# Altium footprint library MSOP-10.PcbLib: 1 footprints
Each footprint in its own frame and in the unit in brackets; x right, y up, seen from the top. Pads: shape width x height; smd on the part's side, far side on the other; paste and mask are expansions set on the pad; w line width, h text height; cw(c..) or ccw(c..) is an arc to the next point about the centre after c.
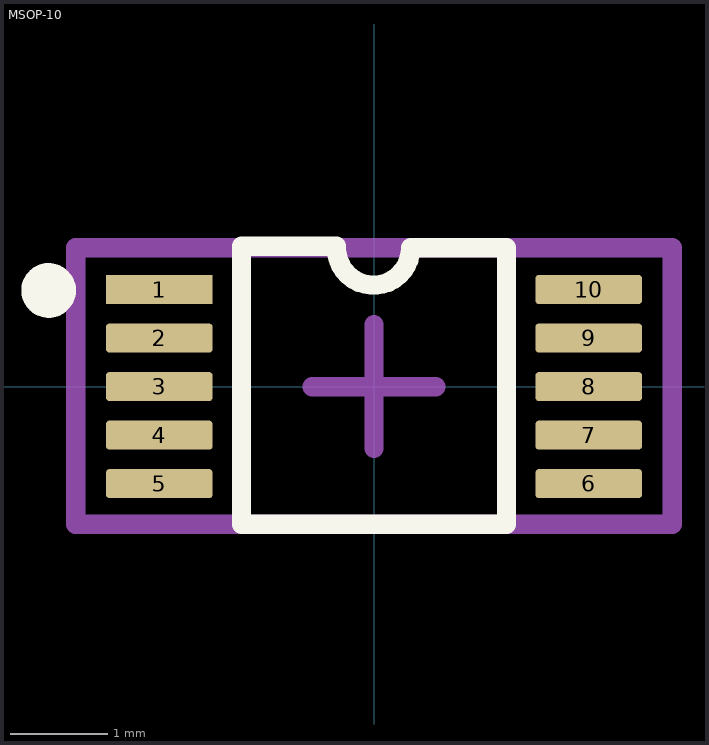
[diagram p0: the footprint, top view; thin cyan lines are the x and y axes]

## MSOP-10 [mm] "5mm x 3.1 mm"
height 1.1
pads (10):
  rect 1.1x0.3 smd: 1(-2.212,1)
  rrect25% 1.1x0.3 smd: 2(-2.212,0.5) 3(-2.212,0) 4(-2.212,-0.5) 5(-2.212,-1) 6(2.212,-1) 7(2.212,-0.5) 8(2.212,0) 9(2.212,0.5) 10(2.212,1)
Top Overlay:
  circle w0.3: c-3.353,0.991 r0.132
  lines w0.2: -0.387,1.427 ccw(c-0.005,1.427) 0.378,1.427 ; -0.387,1.444 -1.365,1.444 -1.365,-1.417 1.365,-1.417 1.365,1.43 0.378,1.43
Mechanical 15:
  lines w0.2: -0.635,0 0.635,0 ; 0,-0.635 0,0.635 ; -3.072,-1.417 -3.072,1.43 3.072,1.43 3.072,-1.417 -3.072,-1.417
3D body "LTC4380HMS-4#PBF.stp": height 1.1, standoff 0, extent -2.45,-1.5 2.45,1.5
